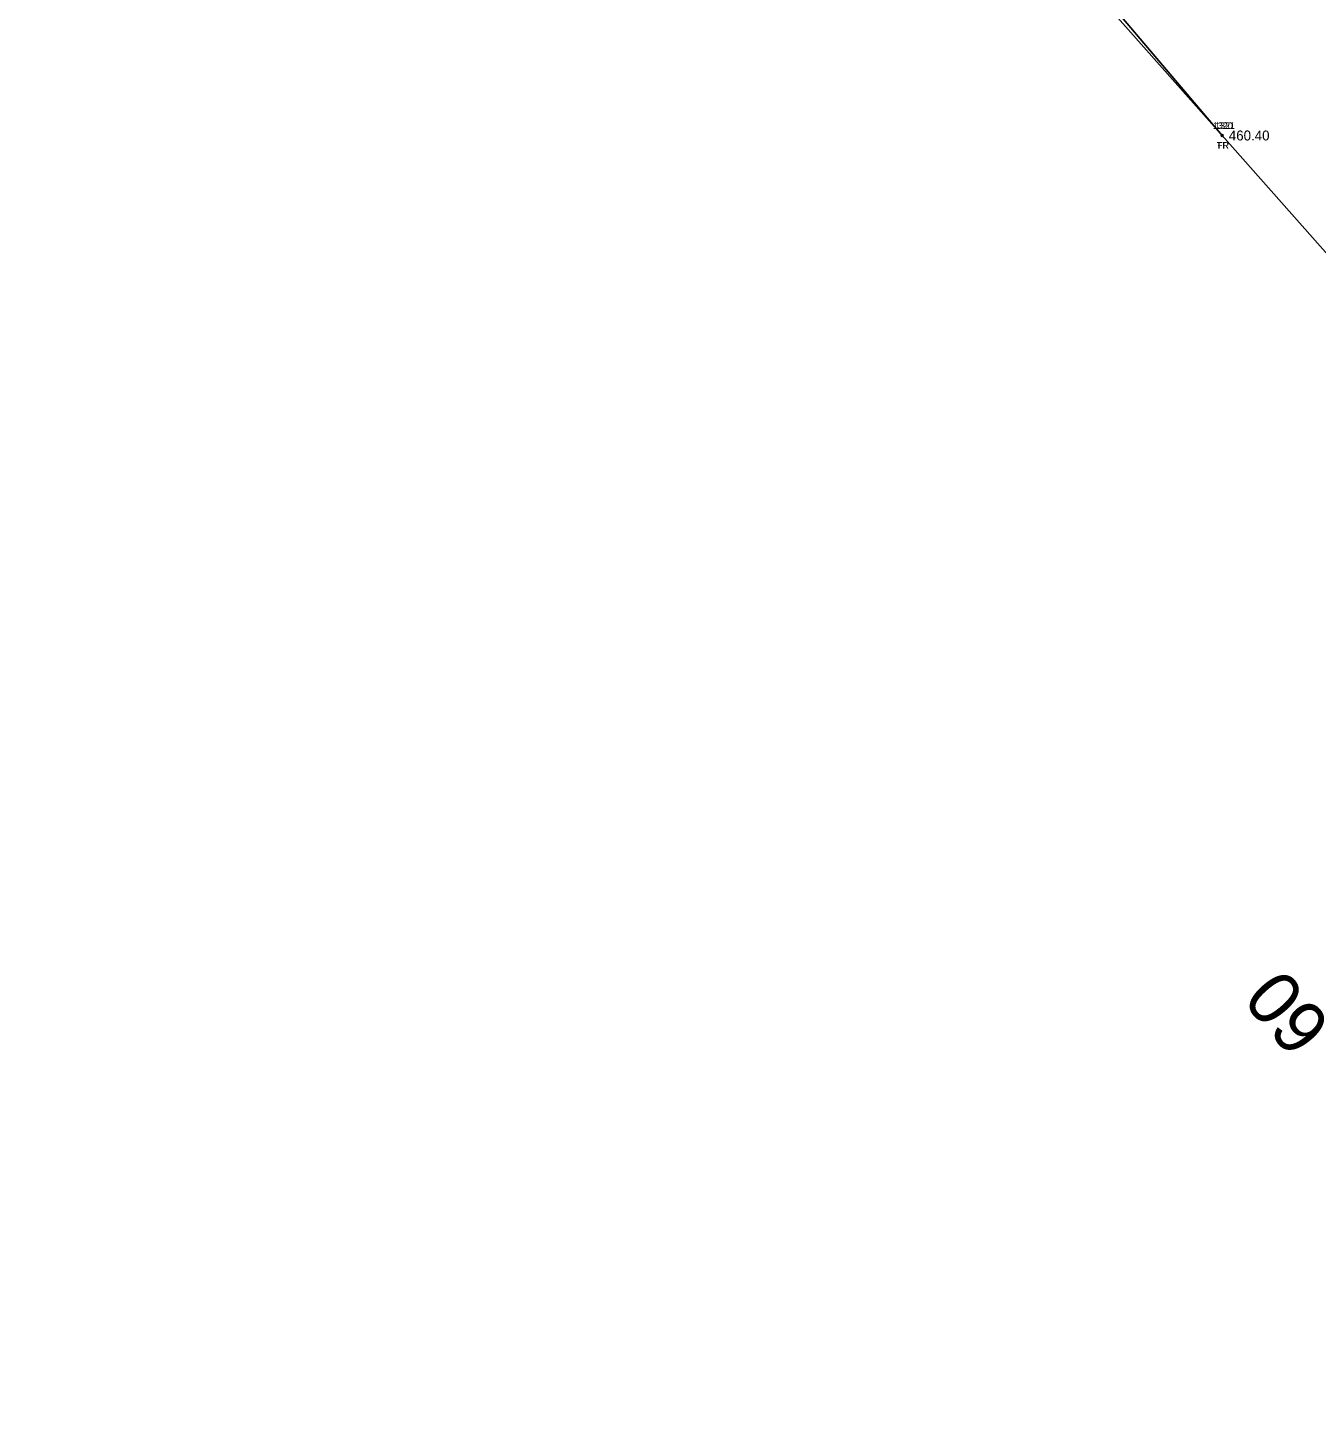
# Model space of a CAD drawing. Extents: x 1745838 to 1751419, y 649211 to 655806.
# Drawn here: x 1749178.8 to 1749372.8, y 650905.5 to 651116.3 of the extents above; entities that cross this region are included whole.
import ezdxf

# ---------------------------------------------------------------- set-up
doc = ezdxf.new("R2010")
doc.units = 0
for name, color, linetype in [('RD_EX_Fence_Other', 7, 'Continuous'), ('RD_EX_Fence_Other_txCode', 7, 'Continuous'), ('RD_EX_TX_Fence_Other_ELEV', 7, 'Continuous'), ('RD_EX_TX_VEG_ELEV', 7, 'Continuous'), ('RD_EX_VEG', 7, 'Continuous'), ('RD_EX_VEG_txCode', 7, 'Continuous'), ('RD_HC_TX_Sta50', 7, 'Continuous'), ('RD_SMD_Locator', 7, 'Continuous')]:
    doc.layers.add(name, color=color, linetype=linetype)

msp = doc.modelspace()

# ---------------------------------------------------------------- linework, layer by layer
at = {"layer": 'RD_EX_Fence_Other'}
msp.add_lwpolyline([(1749228.24, 651202.64), (1749249.97, 651222.14), (1749249.97, 651222.14), (1749291.03, 651176.48), (1749358.68, 651100.15), (1749424.34, 651025.98), (1749461.84, 650986.11), (1749495.25, 650947.39), (1749527.17, 650911.79), (1749559.6, 650874.95), (1749594.11, 650836.92), (1749630.2, 650798.28), (1749673.95, 650750.13)], dxfattribs=at)
at = {"layer": 'RD_EX_VEG'}
msp.add_lwpolyline([(1749178.77, 651203.37), (1749202.73, 651231.24), (1749238.66, 651259.14), (1749294.64, 651175.67), (1749358.68, 651100.15), (1749424.34, 651025.98), (1749461.84, 650986.11), (1749495.25, 650947.39), (1749527.17, 650911.79), (1749559.6, 650874.95), (1749594.11, 650836.92), (1749630.2, 650798.28), (1749696.62, 650725.69)], dxfattribs=at)
at = {"layer": 'RD_SMD_Locator'}
msp.add_circle((1749358.68, 651100.15), 0.15, dxfattribs=at)
msp.add_circle((1749358.68, 651100.15), 0.15, dxfattribs=at)

# ---------------------------------------------------------------- texts
at = {"layer": 'RD_EX_Fence_Other_txCode'}
for s, p in [('1321', (1749357.62, 651101.15)), ('FR', (1749357.93, 651098.15))]:
    msp.add_text(s, height=1, dxfattribs=at).set_placement(p)
at = {"layer": 'RD_EX_TX_Fence_Other_ELEV'}
msp.add_text('460.40', height=1.5, dxfattribs=at).set_placement((1749359.68, 651099.4))
at = {"layer": 'RD_EX_TX_VEG_ELEV'}
msp.add_text('460.40', height=1.5, dxfattribs=at).set_placement((1749359.68, 651099.4))
at = {"layer": 'RD_EX_VEG_txCode'}
for s, p in [('1320', (1749357.3, 651101.15)), ('TR', (1749357.89, 651098.15))]:
    msp.add_text(s, height=1, dxfattribs=at).set_placement(p)
at = {"layer": 'RD_HC_TX_Sta50'}
msp.add_text('60', height=8, rotation=130.8982, dxfattribs=at).set_placement((1749375.4, 650966.11))

doc.saveas('drawing.dxf')
